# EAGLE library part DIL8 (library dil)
SOCKET Dual In Line
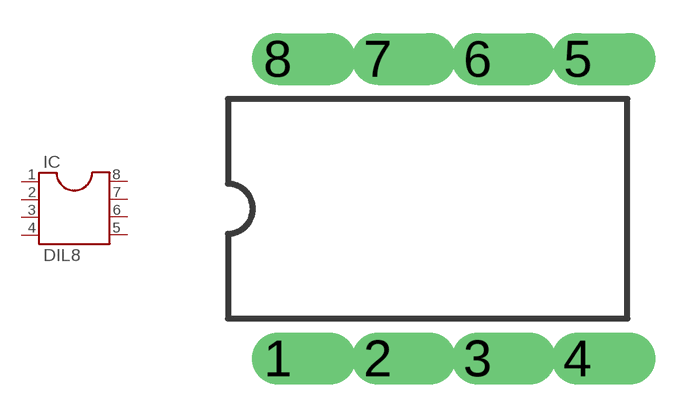
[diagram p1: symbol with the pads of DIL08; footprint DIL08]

Designator prefix IC

## DIL8  [DIL08]
1  1  pas
2  2  pas
3  3  pas
4  4  pas
5  5  pas
6  6  pas
7  7  pas
8  8  pas

## Footprint DIL08 (pad centres in mm)
SOCKET Dual In Line
drill 0.813 offset: 1 -3.81,-3.81; 2 -1.27,-3.81; 3 1.27,-3.81; 4 3.81,-3.81; 5 3.81,3.81; 6 1.27,3.81; 7 -1.27,3.81; 8 -3.81,3.81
